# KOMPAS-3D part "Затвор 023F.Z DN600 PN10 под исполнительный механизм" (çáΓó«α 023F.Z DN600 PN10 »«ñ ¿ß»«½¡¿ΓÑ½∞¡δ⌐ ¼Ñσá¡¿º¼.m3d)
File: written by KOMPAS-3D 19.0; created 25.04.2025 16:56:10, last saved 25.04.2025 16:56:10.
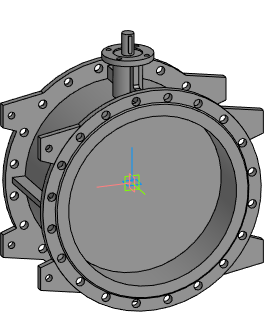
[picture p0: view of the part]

Document properties: Автор: Евгений; Полное имя файла: E:\Dendor Работа Сачек\3D для проекитирвщиков\1.7 Тип 023F.Z Затвор дисковый поворотный фланцевый с двумя эксцентриками\stp_Тип 023F.Z. Затвор под исполн. механизм\Затвор 023F.Z DN600 PN10 под исполнительный механизм.m3d

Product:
- Part/product: Затвор 023F.Z DN600 PN10 под исполнительный механизм

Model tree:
1. Операция без истории:1  (labels: Затвор 023F.Z DN600 PN10 под исполнительный механизм)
